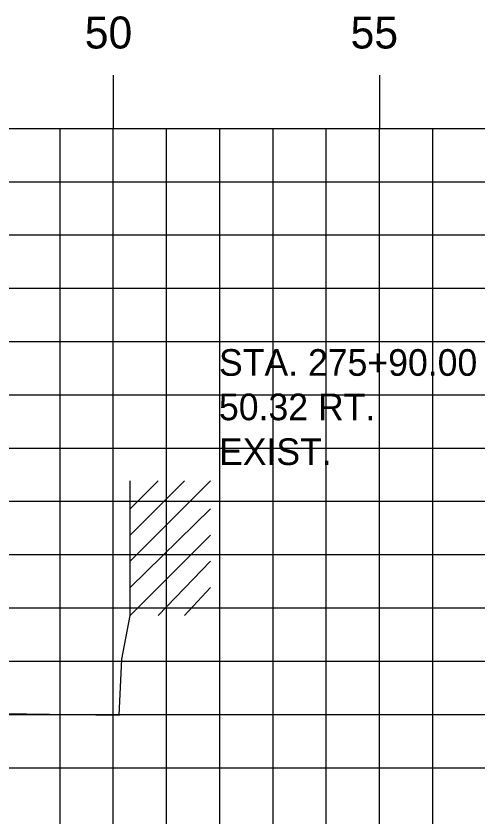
# Model space of a CAD drawing. Extents: x 853563 to 853733, y 366268 to 366378.
# Drawn here: x 853693.94 to 853702.62, y 366334.31 to 366349.35 of the extents above; entities that cross this region are included whole.
import ezdxf

# ---------------------------------------------------------------- set-up
doc = ezdxf.new("R2010")
doc.units = 0
for name, color, linetype in [('D_Text_Monospaced', 7, 'Continuous'), ('H_V ANNOTATION', 7, 'Continuous'), ('MAJOR', 7, 'Continuous'), ('MINOR', 7, 'Continuous'), ('S_Buildings', 7, 'Continuous'), ('S_Roadway_Centerline', 7, 'Continuous')]:
    doc.layers.add(name, color=color, linetype=linetype)

msp = doc.modelspace()

# ---------------------------------------------------------------- linework, layer by layer
at = {"layer": 'MAJOR'}
for p, q in [((853695.768, 366348.238), (853695.768, 366347.236)), ((853700.768, 366348.238), (853700.768, 366347.236)), ((853575.768, 366347.236), (853715.768, 366347.236)), ((853575.768, 366347.236), (853715.768, 366347.236)), ((853695.768, 366327.236), (853695.768, 366347.236)), ((853700.768, 366327.236), (853700.768, 366347.236)), ((853575.768, 366342.236), (853715.768, 366342.236)), ((853575.768, 366337.236), (853715.768, 366337.236))]:
    msp.add_line(p, q, dxfattribs=at)
at = {"layer": 'MINOR'}
for p, q in [((853694.768, 366327.236), (853694.768, 366347.236)), ((853696.768, 366327.236), (853696.768, 366347.236)), ((853697.768, 366327.236), (853697.768, 366347.236)), ((853698.768, 366327.236), (853698.768, 366347.236)), ((853699.768, 366327.236), (853699.768, 366347.236)), ((853701.768, 366327.236), (853701.768, 366347.236)), ((853575.768, 366346.236), (853715.768, 366346.236)), ((853575.768, 366345.236), (853715.768, 366345.236)), ((853575.768, 366344.236), (853715.768, 366344.236)), ((853575.768, 366343.236), (853715.768, 366343.236)), ((853575.768, 366341.236), (853715.768, 366341.236)), ((853575.768, 366340.236), (853715.768, 366340.236)), ((853575.768, 366339.236), (853715.768, 366339.236)), ((853575.768, 366338.236), (853715.768, 366338.236)), ((853575.768, 366336.236), (853715.768, 366336.236)), ((853575.768, 366335.236), (853715.768, 366335.236))]:
    msp.add_line(p, q, dxfattribs=at)
at = {"layer": 'S_Buildings'}
for p, q in [((853696.087, 366338.093), (853696.087, 366340.62)), ((853696.087, 366339.111), (853697.596, 366340.62)), ((853696.087, 366339.603), (853697.104, 366340.62)), ((853696.087, 366340.095), (853696.612, 366340.62)), ((853696.087, 366338.618), (853697.596, 366340.095)), ((853696.087, 366338.093), (853697.596, 366339.603)), ((853696.612, 366338.093), (853697.596, 366339.111)), ((853697.104, 366338.093), (853697.596, 366338.618))]:
    msp.add_line(p, q, dxfattribs=at)
at = {"layer": 'S_Roadway_Centerline'}
msp.add_lwpolyline([(853672.426, 366334.897), (853673.692, 366334.906), (853679.799, 366335.073), (853683.005, 366335.518), (853687.156, 366336.451), (853690.214, 366336.304), (853695.88, 366336.223), (853695.931, 366337.274), (853696.087, 366338.094)], dxfattribs=at)

# ---------------------------------------------------------------- texts
at = {"layer": 'D_Text_Monospaced'}
for s, height, p in [('STA. 275+90.00', 0.49998, (853697.753, 366342.592)), ('50.32 RT.', 0.5, (853697.753, 366341.758)), ('EXIST. ', 0.5, (853697.753, 366340.918))]:
    msp.add_text(s, height=height, dxfattribs=at).set_placement(p)
at = {"layer": 'H_V ANNOTATION'}
for s, p in [('50', (853695.232, 366348.736)), ('55', (853700.224, 366348.736))]:
    msp.add_text(s, height=0.6, dxfattribs=at).set_placement(p)

doc.saveas('drawing.dxf')
